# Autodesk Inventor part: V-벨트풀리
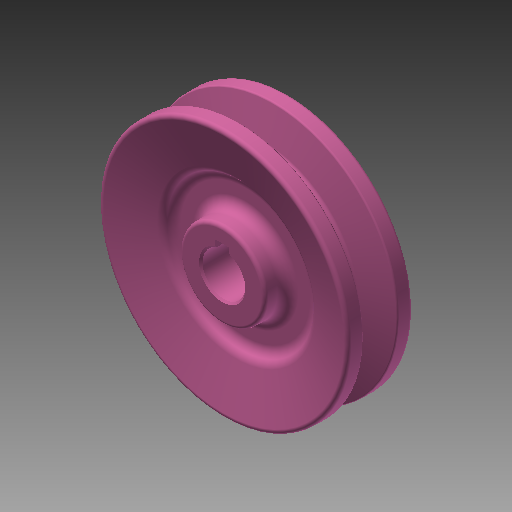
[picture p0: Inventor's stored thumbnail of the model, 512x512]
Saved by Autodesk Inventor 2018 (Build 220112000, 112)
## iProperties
Created: 2016-08
Part Number: V-벨트풀리
Material: 알루미늄 6061
Document SubType Name: Modeling
Designer: mduedu
Density: 2.71 g/cm^3
Appearance: 분홍색
Author: mduedu
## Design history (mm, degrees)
sketch "스케치1"
  geometry: L1 (0, 9.5)-(0, -9.5); L2 (0, 9.5)-(35, 9.5); L3 (35, 9.5)-(35, 4.825); L4 (35, 4.825)-(26, 2.074); L5 (26, 2.074)-(26, 0); L6 (0, 0)-(26, 0); L7 (0, -9.5)-(35, -9.5); L8 (35, -9.5)-(35, -4.825); L9 (35, -4.825)-(26, -2.074); L10 (26, -2.074)-(26, 0); L11 (32.3, 9.5)-(32.3, -9.5); 3 further points
  constraints: 22 end point, 6 point on line, 4 perpendicular, 3 symmetric about line, 1 coincident, 1 horizontal alignment, 1 midpoint, 1 parallel, 1 vertical
  dimensions: "d0" = 19 distance of L1.start L1.end; "d2" = 70 diameter of L8 L1; "d4" = 6.3 distance between parallel lines of L10 L11; "d5" = 2.7 distance between parallel lines of L11 L8; "d6" = 8 distance of point (32.3, -4) point (32.3, 4); "d7" = 34 deg angle of L9 L4
revolve "회전1" sketch "스케치1" stored, may be unused: angle "d8" = 90 deg
sketch "스케치2"
  geometry: L1 (-2, 0)-(2, 0); L2 (2, 0)-(2, 7.8); L3 (2, 7.8)-(-2, 7.8); L4 (-2, 7.8)-(-2, 0); C1 r 6 at (0, 0); 2 further points
  constraints: 8 end point, 2 coincident, 2 parallel, 1 centre point, 1 horizontal, 1 midpoint, 1 perpendicular
  dimensions: "d9" = 12 diameter of C1; "d11" = 4 distance of L2.end L3.end; "d12" = 7.8 distance of L1.end L2.end
extrude "돌출1" cut sketch "스케치2" extent not by distance; stored distance "d13" = 10; taper "d14" = 0 deg
sketch "스케치3"
  geometry: L1 (35, 4.825)-(26, 2.074) reference; L2 (26, 2.074)-(26, -2.074) reference; L3 (0, 0)-(26, 0); L4 (35, 9.5)-(35, 4.825) reference; L5 (-35, 9.5)-(35, 9.5) reference; L6 (35, 9.5)-(21, 5.22); L7 (21, 5.22)-(21, 3); L8 (21, 3)-(12, 3); L9 (12, 3)-(12, 9.5); L10 (0, 9.5)-(0, -9.5); L11 (5.657, -9.5)-(-6, -9.5) reference; L12 (12, 9.5)-(35, 9.5)
  constraints: 14 end point, 3 midpoint, 2 parallel, 2 perpendicular, 2 point on line, 1 collinear, 1 horizontal
  dimensions: "d15" = 3 distance between parallel lines of L3 L8; "d17" = 42 diameter of L7 L10; "d18" = 24 diameter of L9 L10
revolve "회전2" sketch "스케치3" stored, may be unused: angle "d19" = 90 deg
fillet "모깎기1" dims "d20" = 0.5, "d21" = 1, "d22" = 1
fillet "모깎기2" dims "d23" = 3
fillet "모깎기3" dims "d24" = 3
fillet "모깎기4" dims "d25" = 3
chamfer "모따기1" distance "d26" = 0.5; stored, may be unused: second distance "d27" = 2, angle "d28" = 45 deg
fillet "모깎기5" dims "d29" = 1
node "솔리드1"
mirror "대칭1"
